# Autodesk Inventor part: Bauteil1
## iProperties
Created: 2005-12
Part Number: Bauteil1
Document SubType Name: Modeling
Designer: mp
Author: mp
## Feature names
1. Runde Anordnung1 [Circular Pattern]
